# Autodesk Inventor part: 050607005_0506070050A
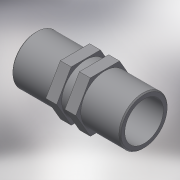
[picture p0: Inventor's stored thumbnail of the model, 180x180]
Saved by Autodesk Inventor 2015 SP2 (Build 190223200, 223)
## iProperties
Created: 2017-05
Part Number: 050607005_0506070050A
Material: Generic
Description: PLASSON NIPPLE 1/2"-1/2"
Document SubType Name: Modeling
Designer: KIM
Density: 1 g/cm^3
Appearance: Default
Author: KIM
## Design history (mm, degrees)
derived "050607.ipt"
feature "Solid1::050607.ipt"
tag "TaggingFeature1"
body "Solid1"
other parameters: "d0" = 47, "d1" = 20.955, "d2" = 22, "d3" = 16.764, "d4" = 17, "d5" = 17, "d6" = 4.7, "d8" = 0.47, "d12" = 0, "H_" = 47, "R_" = 20.955, "E_" = 22, "l_2" = 17
